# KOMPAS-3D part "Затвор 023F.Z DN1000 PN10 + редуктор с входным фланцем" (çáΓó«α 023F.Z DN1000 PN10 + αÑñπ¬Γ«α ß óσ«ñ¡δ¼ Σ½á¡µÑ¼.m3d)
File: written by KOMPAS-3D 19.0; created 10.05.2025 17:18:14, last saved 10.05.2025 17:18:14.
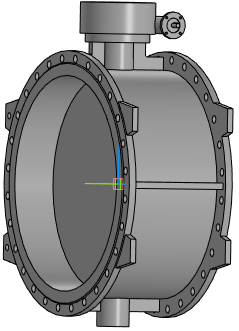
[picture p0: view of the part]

Document properties: Полное имя файла: Затвор 023F.Z DN1000 PN10 + редуктор с входным фланцем.a3d

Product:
- Part/product: Затвор 023F.Z DN1000 PN10 + редуктор с входным фланцем
    Масса: 1313.23

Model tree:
1. Операция без истории:1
